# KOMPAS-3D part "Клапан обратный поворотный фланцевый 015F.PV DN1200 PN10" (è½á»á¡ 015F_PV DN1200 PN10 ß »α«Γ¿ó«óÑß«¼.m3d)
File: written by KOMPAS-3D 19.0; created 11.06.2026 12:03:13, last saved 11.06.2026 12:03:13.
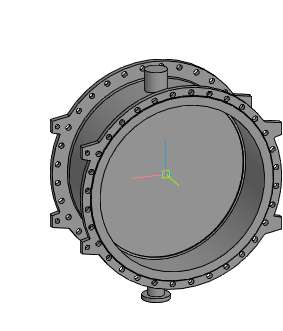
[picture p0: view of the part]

Document properties: Автор: Энергия; Полное имя файла: Z:\3.Личные\kachalov\001_3d для проектировщиков\5.5 Тип 015F.PV Клапан обратный поворотный с двумя эксцентриками\_stp_Клапан 015F.PV DN300-DN1200 с противовесом\Клапан 015F_PV DN1200 PN10 с противовесом.m3d

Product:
- Part/product: Клапан обратный поворотный фланцевый 015F.PV DN1200 PN10

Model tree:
1. Операция без истории:1
2. Сплайн:1
     Координата Y = 30; Координата Z = 600; Вес = 1; Координата X = 1200; Координата Y = 187.983; Координата Z = 600; Вес = 0.333333; Координата X = 1200; Координата Y = 187.983; Координата Z = -600; Вес = 0.333333; Координата Y = 30; Координата Z = -600; Вес = 1; Координата X = -1200; Координата Y = -127.983; Координата Z = -600; Вес = 0.333333; Координата X = -1200; Координата Y = -127.983; Координата Z = 600; Вес = 0.333333; Порядок = 4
